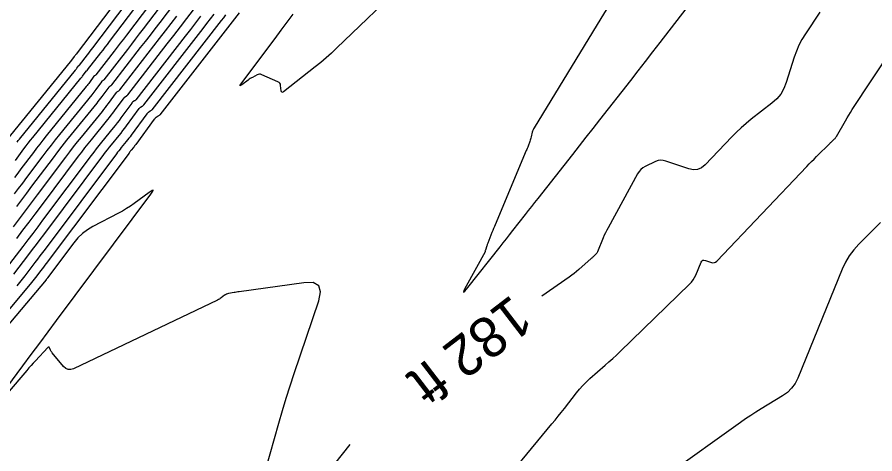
# Model space of a CAD drawing. Extents: x 7585033 to 7595090, y 547091 to 553471.
# Drawn here: x 7587567.9 to 7587701.6, y 548201.8 to 548269.9 of the extents above; entities that cross this region are included whole.
import ezdxf

# ---------------------------------------------------------------- set-up
doc = ezdxf.new("R2010")
doc.units = 0
for name, color, linetype in [('E_TERR_DSPLAY_GeneralTx', 7, 'Continuous'), ('E_TERR_DSPLAY_MajContour', 7, 'Continuous'), ('E_TERR_DSPLAY_MinContour', 7, 'Continuous')]:
    doc.layers.add(name, color=color, linetype=linetype)

msp = doc.modelspace()

# ---------------------------------------------------------------- linework, layer by layer
at = {"layer": 'E_TERR_DSPLAY_MajContour'}
for points in [[(7587597.41, 548290.96), (7587577.1, 548264.13), (7587577.03, 548264.04), (7587576.96, 548263.95), (7587576.89, 548263.86), (7587576.82, 548263.76), (7587576.4, 548263.22), (7587576.39, 548263.21), (7587576.39, 548263.21), (7587576.39, 548263.21), (7587576.38, 548263.21), (7587576.37, 548263.2), (7587576.37, 548263.2), (7587576.36, 548263.19), (7587576.36, 548263.19), (7587576.36, 548263.19), (7587576.26, 548263.05), (7587576.24, 548263.02), (7587576.22, 548263), (7587576.2, 548262.97), (7587576.18, 548262.95), (7587566.19, 548250.66)], [(7587598.81, 548282.96), (7587587.56, 548268.1), (7587586.95, 548267.29), (7587586.33, 548266.48), (7587585.71, 548265.68), (7587585.09, 548264.87), (7587581.4, 548260.12), (7587581.37, 548260.09), (7587581.35, 548260.07), (7587581.32, 548260.04), (7587581.29, 548260.02), (7587581.17, 548259.94), (7587581.14, 548259.92), (7587581.11, 548259.9), (7587581.08, 548259.87), (7587581.06, 548259.84), (7587580.17, 548258.63), (7587580.01, 548258.42), (7587579.85, 548258.21), (7587579.69, 548258), (7587579.53, 548257.79), (7587574.51, 548251.62), (7587573.84, 548250.79), (7587573.19, 548249.96), (7587572.54, 548249.12), (7587571.9, 548248.28), (7587569.36, 548244.88), (7587568.72, 548244.03), (7587568.08, 548243.18), (7587567.44, 548242.34)], [(7587693.02, 548270.68), (7587690.77, 548267.29), (7587690.24, 548266.42), (7587689.77, 548265.53), (7587689.37, 548264.6), (7587689.03, 548263.64), (7587687.78, 548259.69), (7587687.41, 548258.76), (7587686.92, 548257.91), (7587686.3, 548257.16), (7587685.55, 548256.49), (7587682.33, 548253.98), (7587681.53, 548253.34), (7587680.76, 548252.67), (7587680.02, 548251.98), (7587679.3, 548251.25), (7587675.14, 548246.87), (7587674.58, 548246.41), (7587673.97, 548246.16), (7587673.31, 548246.1), (7587672.6, 548246.25), (7587669.02, 548247.47), (7587668.61, 548247.57), (7587668.2, 548247.59), (7587667.8, 548247.53), (7587667.4, 548247.38), (7587665.82, 548246.63), (7587665.45, 548246.42), (7587665.12, 548246.15), (7587664.84, 548245.84), (7587664.61, 548245.48), (7587660.01, 548237.05), (7587659.8, 548236.67), (7587659.61, 548236.28), (7587659.43, 548235.89), (7587659.26, 548235.49), (7587658.36, 548233.32), (7587658.31, 548233.22), (7587658.24, 548233.11), (7587658.17, 548233.02), (7587658.09, 548232.93), (7587657.74, 548232.59), (7587657.65, 548232.51), (7587657.56, 548232.42), (7587657.47, 548232.34), (7587657.38, 548232.26), (7587655.44, 548230.55), (7587655.08, 548230.25), (7587654.72, 548229.95), (7587654.35, 548229.66), (7587653.96, 548229.39), (7587649.68, 548226.38)], [(7587596.5, 548270.05), (7587595.71, 548269.01), (7587594.91, 548267.97), (7587594.11, 548266.94), (7587586.4, 548257.02), (7587586.35, 548256.97), (7587586.31, 548256.92), (7587586.25, 548256.88), (7587586.2, 548256.84), (7587585.96, 548256.69), (7587585.9, 548256.65), (7587585.85, 548256.61), (7587585.8, 548256.56), (7587585.76, 548256.5), (7587584.08, 548254.21), (7587583.79, 548253.81), (7587583.49, 548253.42), (7587583.18, 548253.03), (7587582.87, 548252.64), (7587581.04, 548250.39), (7587580.64, 548249.88), (7587580.23, 548249.37), (7587579.84, 548248.86), (7587579.45, 548248.34), (7587571.88, 548238.23), (7587571.11, 548237.21), (7587570.34, 548236.19), (7587569.57, 548235.17), (7587568.79, 548234.16), (7587565.7, 548230.1)], [(7587563.04, 548207.78), (7587568.81, 548215.55), (7587570.11, 548217.31), (7587571.42, 548219.07), (7587572.74, 548220.83), (7587574.05, 548222.59), (7587588.77, 548242.29), (7587589.08, 548242.75), (7587589.13, 548242.95), (7587588.93, 548242.9), (7587588.47, 548242.59), (7587586.15, 548240.87), (7587585.56, 548240.45), (7587584.95, 548240.05), (7587584.33, 548239.68), (7587583.7, 548239.33), (7587579.7, 548237.24), (7587578.85, 548236.74), (7587578.08, 548236.15), (7587577.38, 548235.48), (7587576.75, 548234.73), (7587572.64, 548229.25), (7587572.62, 548229.22), (7587572.6, 548229.2), (7587572.59, 548229.17), (7587572.57, 548229.15), (7587572.49, 548229.05), (7587572.47, 548229.03), (7587572.45, 548229), (7587572.44, 548228.98), (7587572.42, 548228.96), (7587561.27, 548215.73)], [(7587605.99, 548197.04), (7587608.71, 548206.63), (7587609.27, 548208.57), (7587609.86, 548210.51), (7587610.47, 548212.43), (7587611.11, 548214.35), (7587614.94, 548225.66), (7587615.21, 548227.08), (7587614.91, 548228.04), (7587614.04, 548228.51), (7587612.58, 548228.5), (7587602.51, 548227.09), (7587602.31, 548227.06), (7587602.11, 548227.03), (7587601.91, 548227), (7587601.71, 548226.96), (7587600.85, 548226.8), (7587600.69, 548226.76), (7587600.53, 548226.71), (7587600.39, 548226.63), (7587600.25, 548226.54), (7587599.71, 548226.14), (7587599.57, 548226.04), (7587599.43, 548225.95), (7587599.28, 548225.87), (7587599.13, 548225.8), (7587576.71, 548215.09), (7587576.27, 548214.95), (7587575.87, 548214.96), (7587575.49, 548215.12), (7587575.15, 548215.43), (7587573.35, 548217.59), (7587573.29, 548217.68), (7587573.22, 548217.77), (7587573.17, 548217.86), (7587573.12, 548217.96), (7587572.93, 548218.36), (7587572.88, 548218.44), (7587572.82, 548218.47), (7587572.76, 548218.46), (7587572.68, 548218.4), (7587570.76, 548216.34), (7587570.42, 548215.96), (7587570.08, 548215.59), (7587569.74, 548215.21), (7587569.41, 548214.82), (7587563.24, 548207.63)], [(7587619.77, 548203.28), (7587615.2, 548197.49)]]:
    msp.add_lwpolyline(points, dxfattribs=at)
at = {"layer": 'E_TERR_DSPLAY_MinContour'}
for points in [[(7587567.89, 548250.41), (7587568.08, 548250.66), (7587568.27, 548250.9), (7587577.02, 548261.66), (7587577.07, 548261.73), (7587577.13, 548261.8), (7587577.18, 548261.87), (7587577.23, 548261.94), (7587577.53, 548262.35), (7587577.54, 548262.36), (7587577.55, 548262.37), (7587577.56, 548262.38), (7587577.57, 548262.38), (7587577.61, 548262.41), (7587577.62, 548262.42), (7587577.63, 548262.43), (7587577.64, 548262.43), (7587577.65, 548262.44), (7587578.89, 548264.04), (7587579.1, 548264.31), (7587579.31, 548264.58), (7587579.51, 548264.85), (7587579.72, 548265.12), (7587597.76, 548288.96)], [(7587567.63, 548247.57), (7587568.97, 548249.37), (7587569.31, 548249.82), (7587569.65, 548250.26), (7587570, 548250.7), (7587570.35, 548251.14), (7587577.85, 548260.37), (7587577.95, 548260.49), (7587578.04, 548260.6), (7587578.12, 548260.72), (7587578.21, 548260.84), (7587578.71, 548261.52), (7587578.72, 548261.53), (7587578.74, 548261.55), (7587578.75, 548261.56), (7587578.77, 548261.57), (7587578.84, 548261.61), (7587578.85, 548261.63), (7587578.87, 548261.64), (7587578.88, 548261.65), (7587578.9, 548261.67), (7587580.96, 548264.32), (7587581.3, 548264.77), (7587581.65, 548265.21), (7587581.99, 548265.66), (7587582.33, 548266.11), (7587598.11, 548286.96)], [(7587659.73, 548271.06), (7587658.89, 548269.69), (7587648.49, 548252.65), (7587648.4, 548252.49), (7587648.33, 548252.32), (7587648.26, 548252.15), (7587648.21, 548251.97), (7587648.04, 548251.24), (7587648, 548251.06), (7587647.95, 548250.89), (7587647.89, 548250.71), (7587647.83, 548250.53), (7587647.56, 548249.81), (7587647.49, 548249.63), (7587647.42, 548249.45), (7587647.35, 548249.28), (7587647.27, 548249.1), (7587642.42, 548237.55), (7587642.29, 548237.24), (7587642.17, 548236.93), (7587642.04, 548236.62), (7587641.92, 548236.31), (7587641.28, 548234.68), (7587641.23, 548234.57), (7587641.19, 548234.46), (7587641.15, 548234.34), (7587641.11, 548234.23), (7587640.9, 548233.58), (7587640.89, 548233.55), (7587640.88, 548233.53), (7587640.88, 548233.51), (7587640.88, 548233.49), (7587640.88, 548233.39), (7587640.88, 548233.37), (7587640.87, 548233.35), (7587640.87, 548233.33), (7587640.86, 548233.31), (7587637.89, 548227.96), (7587637.53, 548227.27), (7587637.46, 548227.01), (7587637.67, 548227.18), (7587638.16, 548227.77), (7587643.18, 548234.11), (7587643.67, 548234.74), (7587644.17, 548235.36), (7587644.67, 548235.99), (7587645.16, 548236.62), (7587647.14, 548239.14), (7587647.63, 548239.77), (7587648.13, 548240.4), (7587648.62, 548241.03), (7587649.12, 548241.65), (7587654.5, 548248.49), (7587655.56, 548249.84), (7587656.62, 548251.19), (7587657.68, 548252.54), (7587658.74, 548253.89), (7587663.55, 548260.04), (7587664.7, 548261.52), (7587665.85, 548262.99), (7587667, 548264.48), (7587668.14, 548265.96), (7587684.36, 548287.02)], [(7587598.46, 548284.96), (7587584.95, 548267.11), (7587584.47, 548266.48), (7587583.99, 548265.85), (7587583.51, 548265.22), (7587583.02, 548264.6), (7587580.15, 548260.89), (7587580.13, 548260.87), (7587580.11, 548260.85), (7587580.09, 548260.83), (7587580.06, 548260.82), (7587579.97, 548260.76), (7587579.94, 548260.74), (7587579.92, 548260.72), (7587579.9, 548260.7), (7587579.88, 548260.68), (7587579.19, 548259.73), (7587579.07, 548259.57), (7587578.94, 548259.41), (7587578.82, 548259.24), (7587578.69, 548259.08), (7587572.43, 548251.38), (7587571.92, 548250.75), (7587571.42, 548250.11), (7587570.92, 548249.47), (7587570.44, 548248.82), (7587568.49, 548246.23), (7587568, 548245.58), (7587567.52, 548244.93)], [(7587567.85, 548240.39), (7587568.64, 548241.44), (7587569.43, 548242.48), (7587570.22, 548243.53), (7587573.55, 548247.97), (7587574.25, 548248.9), (7587574.95, 548249.81), (7587575.67, 548250.72), (7587576.39, 548251.62), (7587580.36, 548256.51), (7587580.56, 548256.76), (7587580.76, 548257.01), (7587580.96, 548257.27), (7587581.15, 548257.52), (7587582.24, 548259.01), (7587582.26, 548259.04), (7587582.29, 548259.08), (7587582.33, 548259.1), (7587582.36, 548259.13), (7587582.52, 548259.23), (7587582.55, 548259.25), (7587582.59, 548259.28), (7587582.62, 548259.31), (7587582.65, 548259.34), (7587587.16, 548265.15), (7587587.92, 548266.13), (7587588.68, 548267.11), (7587589.43, 548268.1), (7587590.18, 548269.09), (7587599.17, 548280.96)], [(7587628.52, 548275.53), (7587617.71, 548265.06), (7587616.9, 548264.3), (7587616.07, 548263.56), (7587615.23, 548262.84), (7587614.36, 548262.14), (7587609.44, 548258.27), (7587609.3, 548258.19), (7587609.19, 548258.18), (7587609.11, 548258.27), (7587609.07, 548258.43), (7587608.98, 548259.26), (7587608.94, 548259.45), (7587608.86, 548259.62), (7587608.73, 548259.74), (7587608.56, 548259.84), (7587606.04, 548260.93), (7587605.85, 548260.99), (7587605.67, 548261), (7587605.49, 548260.98), (7587605.31, 548260.9), (7587604.6, 548260.52), (7587604.42, 548260.43), (7587604.25, 548260.32), (7587604.08, 548260.21), (7587603.92, 548260.1), (7587602.91, 548259.36), (7587602.74, 548259.24), (7587602.66, 548259.22), (7587602.68, 548259.3), (7587602.79, 548259.47), (7587608.12, 548266.59), (7587609.06, 548267.85), (7587610, 548269.1), (7587610.95, 548270.36)], [(7587567.85, 548235.41), (7587568.81, 548236.67), (7587569.77, 548237.94), (7587570.73, 548239.21), (7587571.68, 548240.48), (7587577.48, 548248.22), (7587577.97, 548248.87), (7587578.47, 548249.52), (7587578.98, 548250.16), (7587579.49, 548250.8), (7587582.03, 548253.93), (7587582.31, 548254.27), (7587582.58, 548254.61), (7587582.84, 548254.96), (7587583.1, 548255.32), (7587584.59, 548257.34), (7587584.62, 548257.39), (7587584.67, 548257.43), (7587584.71, 548257.47), (7587584.76, 548257.5), (7587584.97, 548257.63), (7587585.02, 548257.67), (7587585.07, 548257.71), (7587585.11, 548257.75), (7587585.15, 548257.79), (7587591.31, 548265.72), (7587592.34, 548267.05), (7587593.36, 548268.38), (7587594.38, 548269.71), (7587595.4, 548271.05)], [(7587602.49, 548270.58), (7587590.15, 548254.7), (7587590.09, 548254.62), (7587590.02, 548254.56), (7587589.95, 548254.5), (7587589.88, 548254.45), (7587589.56, 548254.25), (7587589.48, 548254.19), (7587589.41, 548254.14), (7587589.35, 548254.07), (7587589.29, 548254), (7587586.39, 548250.04), (7587586.31, 548249.93), (7587586.22, 548249.82), (7587586.13, 548249.71), (7587586.05, 548249.6), (7587585.69, 548249.16), (7587585.6, 548249.05), (7587585.52, 548248.94), (7587585.43, 548248.83), (7587585.35, 548248.71), (7587572.45, 548231.49), (7587572.24, 548231.22), (7587572.04, 548230.95), (7587571.83, 548230.67), (7587571.62, 548230.4), (7587570.79, 548229.31), (7587570.58, 548229.04), (7587570.37, 548228.77), (7587570.16, 548228.51), (7587569.94, 548228.25), (7587560.11, 548216.58)], [(7587567.32, 548237.2), (7587568.27, 548238.45), (7587569.21, 548239.69), (7587570.15, 548240.94), (7587571.08, 548242.18), (7587575.51, 548248.1), (7587576.11, 548248.89), (7587576.71, 548249.67), (7587577.32, 548250.44), (7587577.94, 548251.21), (7587581.2, 548255.22), (7587581.44, 548255.51), (7587581.67, 548255.81), (7587581.9, 548256.11), (7587582.13, 548256.42), (7587583.41, 548258.17), (7587583.44, 548258.21), (7587583.48, 548258.25), (7587583.52, 548258.29), (7587583.56, 548258.32), (7587583.74, 548258.43), (7587583.79, 548258.46), (7587583.83, 548258.49), (7587583.86, 548258.53), (7587583.9, 548258.57), (7587589.23, 548265.43), (7587590.12, 548266.59), (7587591.02, 548267.75), (7587591.91, 548268.91), (7587592.79, 548270.08)], [(7587567.4, 548229.83), (7587569.74, 548232.91), (7587570.32, 548233.67), (7587570.91, 548234.44), (7587571.49, 548235.22), (7587572.07, 548235.99), (7587581.41, 548248.47), (7587581.7, 548248.85), (7587582, 548249.23), (7587582.29, 548249.61), (7587582.59, 548249.98), (7587583.8, 548251.47), (7587584.1, 548251.84), (7587584.4, 548252.22), (7587584.69, 548252.6), (7587584.97, 548252.98), (7587586.94, 548255.67), (7587586.99, 548255.73), (7587587.04, 548255.78), (7587587.1, 548255.83), (7587587.16, 548255.88), (7587587.42, 548256.04), (7587587.49, 548256.08), (7587587.55, 548256.13), (7587587.6, 548256.19), (7587587.65, 548256.25), (7587596.9, 548268.15), (7587597.48, 548268.9), (7587598.05, 548269.64), (7587598.62, 548270.39)], [(7587600.4, 548270.27), (7587600.05, 548269.82), (7587599.7, 548269.37), (7587588.9, 548255.47), (7587588.84, 548255.41), (7587588.78, 548255.35), (7587588.72, 548255.29), (7587588.65, 548255.24), (7587588.36, 548255.06), (7587588.29, 548255.01), (7587588.22, 548254.96), (7587588.17, 548254.9), (7587588.11, 548254.83), (7587585.68, 548251.51), (7587585.5, 548251.26), (7587585.31, 548251.02), (7587585.12, 548250.77), (7587584.92, 548250.53), (7587584.14, 548249.57), (7587583.95, 548249.33), (7587583.76, 548249.08), (7587583.57, 548248.84), (7587583.38, 548248.59), (7587572.26, 548233.74), (7587571.87, 548233.22), (7587571.47, 548232.7), (7587571.08, 548232.17), (7587570.68, 548231.65), (7587569.09, 548229.57), (7587568.7, 548229.06), (7587568.29, 548228.54), (7587567.88, 548228.04)], [(7587645.91, 548200), (7587651.27, 548206.49), (7587651.76, 548207.08), (7587652.24, 548207.68), (7587652.72, 548208.29), (7587653.2, 548208.89), (7587655.09, 548211.32), (7587655.58, 548211.92), (7587656.09, 548212.49), (7587656.63, 548213.03), (7587657.19, 548213.55), (7587659.57, 548215.65), (7587660.16, 548216.17), (7587660.74, 548216.7), (7587661.31, 548217.23), (7587661.88, 548217.78), (7587672.71, 548228.27), (7587673.01, 548228.59), (7587673.27, 548228.94), (7587673.49, 548229.31), (7587673.68, 548229.7), (7587674.51, 548231.69), (7587674.62, 548231.88), (7587674.77, 548232), (7587674.96, 548232.03), (7587675.18, 548231.99), (7587676.13, 548231.67), (7587676.37, 548231.62), (7587676.58, 548231.64), (7587676.78, 548231.72), (7587676.96, 548231.87), (7587691, 548246.63), (7587691.37, 548247.02), (7587691.74, 548247.4), (7587692.12, 548247.78), (7587692.5, 548248.16), (7587694.61, 548250.26), (7587694.69, 548250.34), (7587694.78, 548250.42), (7587694.87, 548250.51), (7587694.95, 548250.59), (7587695.3, 548250.91), (7587695.39, 548251), (7587695.46, 548251.09), (7587695.53, 548251.18), (7587695.6, 548251.28), (7587697, 548253.75), (7587697.26, 548254.19), (7587697.52, 548254.63), (7587697.79, 548255.06), (7587698.07, 548255.49), (7587707.48, 548269.67)], [(7587702.5, 548237.89), (7587699.1, 548234.52), (7587698.3, 548233.64), (7587697.6, 548232.7), (7587697, 548231.69), (7587696.5, 548230.62), (7587689.59, 548213.63), (7587689.17, 548212.79), (7587688.63, 548212.04), (7587687.98, 548211.39), (7587687.21, 548210.84), (7587683.9, 548208.84), (7587683.07, 548208.33), (7587682.26, 548207.8), (7587681.46, 548207.26), (7587680.67, 548206.71), (7587669.19, 548198.48)]]:
    msp.add_lwpolyline(points, dxfattribs=at)

# ---------------------------------------------------------------- texts
at = {"layer": 'E_TERR_DSPLAY_GeneralTx'}
msp.add_text('182 ft', height=6.3, rotation=217.4902, dxfattribs=at).set_placement((7587645, 548226.79))

doc.saveas('drawing.dxf')
